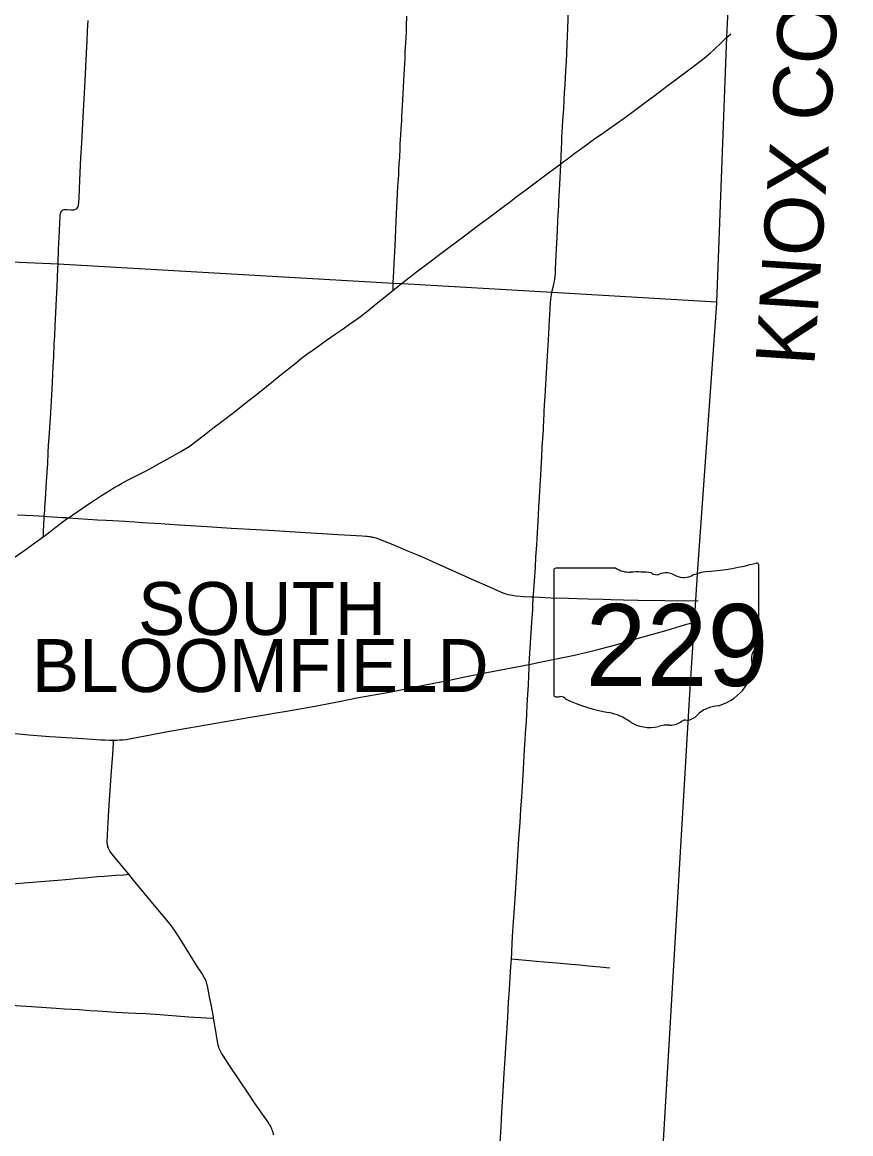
# Model space of a CAD drawing. Extents: x 9078 to 9739, y 4248 to 4966.
# Drawn here: x 9587.6 to 9658, y 4332.5 to 4427 of the extents above; entities that cross this region are included whole.
import ezdxf

# ---------------------------------------------------------------- set-up
doc = ezdxf.new("R2010")
doc.units = 0
for name, color, linetype in [('GM_X_Adjacent_County_Text', 7, 'Continuous'), ('GM_X_County', 7, 'Continuous'), ('GM_X_County_Road', 7, 'Continuous'), ('GM_X_State_Route', 7, 'Continuous'), ('GM_X_State_Shield', 7, 'Continuous'), ('GM_X_Township', 7, 'Continuous'), ('GM_X_Township_Road', 7, 'Continuous'), ('GM_X_Township_Text', 7, 'Continuous')]:
    doc.layers.add(name, color=color, linetype=linetype)

msp = doc.modelspace()

# ---------------------------------------------------------------- linework, layer by layer
at = {"layer": 'GM_X_County'}
msp.add_lwpolyline([(9647.546, 4428.546), (9647.413, 4425.737), (9646.564, 4403.186), (9646.559, 4403.067), (9644.937, 4380.525), (9644.771, 4377.858), (9644.659, 4376.066), (9644.246, 4369.414), (9641.706, 4326.626), (9641.572, 4325.525), (9640.943, 4314.304), (9639.941, 4298.12), (9639.533, 4291.393), (9638.883, 4280.676), (9638.292, 4270.922), (9624.366, 4271.807), (9610.553, 4272.683), (9582.743, 4274.463), (9578.044, 4274.834), (9548.202, 4276.71), (9527.732, 4277.916), (9504.96, 4279.335)], dxfattribs=at)
at = {"layer": 'GM_X_County_Road'}
for points in [[(9633.407, 4416.682), (9633.43, 4417.189), (9633.454, 4417.596), (9633.514, 4418.576), (9633.58, 4419.641), (9633.66, 4420.986), (9633.695, 4421.655), (9633.754, 4422.834), (9633.804, 4423.652), (9633.846, 4424.307), (9633.883, 4425.126), (9633.906, 4425.753), (9633.928, 4426.436), (9633.959, 4427.257), (9633.99, 4427.995), (9634.012, 4428.487), (9634.034, 4428.896), (9634.056, 4429.273), (9634.059, 4429.334)], [(9633.332, 4414.942), (9633.536, 4415.095), (9633.866, 4415.338), (9634.439, 4415.78), (9634.914, 4416.127), (9635.51, 4416.562), (9635.774, 4416.755), (9636.307, 4417.134), (9636.778, 4417.46), (9637.384, 4417.88), (9638.056, 4418.351), (9638.723, 4418.829), (9639.71, 4419.564), (9640.503, 4420.147), (9641.358, 4420.784), (9642.342, 4421.522), (9643.065, 4422.062), (9644.442, 4423.097), (9645.36, 4423.787), (9645.681, 4424.043), (9646.056, 4424.363), (9646.297, 4424.585), (9647, 4425.274), (9647.355, 4425.613), (9647.773, 4425.972)], [(9633.332, 4414.942), (9633.35, 4415.469), (9633.39, 4416.288), (9633.407, 4416.682)], [(9619.77, 4404.734), (9619.905, 4404.843), (9620.42, 4405.25), (9621.07, 4405.749), (9621.723, 4406.246), (9623.033, 4407.232), (9625.267, 4408.902), (9626.118, 4409.544), (9626.578, 4409.887), (9627.17, 4410.327), (9627.631, 4410.666), (9628.089, 4411.012), (9628.937, 4411.658), (9629.525, 4412.105), (9630.248, 4412.644), (9631.501, 4413.571), (9632.288, 4414.162), (9633.332, 4414.942)], [(9633.133, 4410.935), (9633.155, 4411.38), (9633.178, 4411.789), (9633.201, 4412.198), (9633.275, 4413.755), (9633.305, 4414.324), (9633.33, 4414.894), (9633.332, 4414.942)], [(9632.576, 4404.003), (9632.603, 4404.133), (9632.678, 4404.442), (9632.744, 4404.71), (9632.788, 4404.926), (9632.832, 4405.186), (9632.872, 4405.552), (9632.894, 4405.997), (9632.942, 4407.147), (9632.964, 4407.724), (9633.016, 4408.681), (9633.051, 4409.336), (9633.09, 4410.073), (9633.116, 4410.563), (9633.133, 4410.935)], [(9619.091, 4404.19), (9619.77, 4404.734)], [(9591.52, 4384.854), (9591.886, 4385.114), (9592.703, 4385.662), (9593.18, 4385.981), (9593.724, 4386.348), (9594.341, 4386.749), (9594.824, 4387.057), (9595.379, 4387.406), (9595.732, 4387.613), (9596.019, 4387.769), (9596.6, 4388.073), (9596.889, 4388.227), (9597.399, 4388.491), (9598.056, 4388.826), (9598.419, 4389.018), (9599.283, 4389.488), (9599.714, 4389.726), (9600.359, 4390.084), (9601.077, 4390.482), (9601.502, 4390.731), (9601.779, 4390.908), (9601.98, 4391.052), (9602.24, 4391.252), (9603.206, 4392.007), (9603.788, 4392.458), (9604.439, 4392.957), (9605.026, 4393.405), (9605.48, 4393.756), (9605.868, 4394.058), (9606.769, 4394.766), (9607.088, 4395.021), (9607.732, 4395.528), (9608.946, 4396.505), (9609.583, 4397.023), (9610.734, 4397.947), (9611.311, 4398.406), (9611.769, 4398.751), (9612.304, 4399.129), (9612.906, 4399.556), (9613.441, 4399.937), (9614.181, 4400.452), (9614.852, 4400.924), (9615.387, 4401.301), (9615.923, 4401.68), (9616.319, 4401.973), (9616.965, 4402.479), (9617.667, 4403.046), (9618.434, 4403.662), (9619.091, 4404.19)], [(9631.008, 4378.13), (9631.021, 4378.342), (9631.097, 4379.487), (9631.172, 4380.633), (9631.225, 4381.534), (9631.285, 4382.517), (9631.318, 4383.09), (9631.373, 4384.072), (9631.433, 4385.055), (9631.478, 4385.792), (9631.526, 4386.611), (9631.61, 4388.084), (9631.627, 4388.411), (9631.658, 4389.066), (9631.713, 4390.049), (9631.761, 4390.868), (9631.808, 4391.605), (9631.849, 4392.341), (9631.867, 4392.669), (9631.882, 4392.996), (9631.924, 4393.815), (9631.955, 4394.47), (9631.992, 4395.126), (9632.023, 4395.699), (9632.05, 4396.19), (9632.107, 4397.172), (9632.162, 4398.153), (9632.221, 4399.051), (9632.279, 4399.951), (9632.312, 4400.524), (9632.339, 4401.015), (9632.376, 4401.753), (9632.39, 4401.999), (9632.431, 4402.737), (9632.489, 4403.45), (9632.537, 4403.816), (9632.576, 4404.003)], [(9589.383, 4383.25), (9589.456, 4383.303), (9590.046, 4383.745), (9590.629, 4384.197), (9591.419, 4384.782), (9591.52, 4384.854)], [(9591.52, 4384.854), (9592.339, 4384.787), (9593.156, 4384.735), (9593.975, 4384.689), (9594.712, 4384.648), (9596.347, 4384.558), (9597.165, 4384.503), (9597.819, 4384.459), (9598.8, 4384.402), (9599.373, 4384.369), (9600.109, 4384.321), (9600.928, 4384.27), (9603.302, 4384.113), (9605.338, 4383.985), (9607.467, 4383.863), (9609.023, 4383.766), (9611.234, 4383.631), (9614.42, 4383.434), (9616.467, 4383.316), (9616.765, 4383.298), (9616.887, 4383.289), (9617.039, 4383.266), (9617.14, 4383.252), (9617.255, 4383.233), (9617.322, 4383.219), (9617.41, 4383.199), (9617.504, 4383.176), (9617.612, 4383.143), (9617.769, 4383.093), (9618.141, 4382.958), (9619.353, 4382.462), (9620.185, 4382.116), (9620.867, 4381.833), (9621.769, 4381.44), (9622.744, 4381.007), (9626.036, 4379.528), (9627.085, 4379.061), (9628.21, 4378.562), (9628.407, 4378.482), (9628.593, 4378.416), (9628.744, 4378.371), (9628.874, 4378.337), (9629.046, 4378.298), (9629.231, 4378.267), (9629.486, 4378.237), (9629.884, 4378.194), (9630.156, 4378.172), (9630.844, 4378.138), (9631.008, 4378.13)], [(9586.453, 4381.158), (9587.726, 4382.057), (9588.661, 4382.724), (9589.383, 4383.25)], [(9630.656, 4372.402), (9630.657, 4372.449), (9630.712, 4373.35), (9630.906, 4376.379), (9630.946, 4377.034), (9630.968, 4377.443), (9630.999, 4378.015), (9631.008, 4378.13)], [(9631.008, 4378.13), (9632.505, 4378.058), (9633.981, 4378.012), (9634.718, 4377.995), (9635.62, 4377.97), (9636.933, 4377.936), (9637.589, 4377.922), (9638.653, 4377.897), (9639.882, 4377.867), (9642.179, 4377.836), (9644.996, 4377.797)], [(9629.135, 4347.38), (9629.162, 4347.912), (9629.211, 4348.731), (9629.271, 4349.713), (9629.445, 4352.496), (9629.57, 4354.296), (9629.658, 4355.673), (9629.753, 4357.143), (9629.779, 4357.552), (9629.826, 4358.288), (9629.871, 4358.942), (9629.95, 4360.088), (9630.023, 4361.152), (9630.074, 4362.053), (9630.104, 4362.544), (9630.16, 4363.526), (9630.257, 4365.163), (9630.309, 4365.981), (9630.347, 4366.554), (9630.406, 4367.536), (9630.444, 4368.191), (9630.483, 4368.929), (9630.513, 4369.42), (9630.557, 4370.237), (9630.576, 4370.647), (9630.613, 4371.384), (9630.646, 4372.121), (9630.656, 4372.402)], [(9627.886, 4327.412), (9627.948, 4328.25), (9628.066, 4330.13), (9628.174, 4331.764), (9628.257, 4333.072), (9628.3, 4333.807), (9628.359, 4334.788), (9628.435, 4336.096), (9628.529, 4337.649), (9628.58, 4338.466), (9628.636, 4339.365), (9628.716, 4340.673), (9628.826, 4342.389), (9628.901, 4343.697), (9628.965, 4344.76), (9629.066, 4346.312), (9629.135, 4347.38)]]:
    msp.add_lwpolyline(points, dxfattribs=at)
at = {"layer": 'GM_X_State_Route'}
msp.add_lwpolyline([(9586.691, 4366.542), (9588.159, 4366.411), (9589.952, 4366.276), (9592.324, 4366.122), (9593.552, 4366.042), (9594.26, 4365.996), (9594.612, 4365.976), (9595.005, 4365.961), (9595.351, 4365.956), (9595.606, 4365.963), (9595.86, 4365.972), (9596.128, 4365.994), (9596.412, 4366.023), (9597.138, 4366.143), (9598.49, 4366.42), (9599.779, 4366.671), (9600.91, 4366.868), (9605.519, 4367.663), (9606.812, 4367.886), (9608.025, 4368.086), (9608.995, 4368.251), (9610.046, 4368.433), (9611.825, 4368.735), (9613.357, 4369.016), (9614.642, 4369.281), (9616.01, 4369.555), (9618.916, 4370.079), (9621.007, 4370.49), (9621.967, 4370.681), (9623.752, 4371.036), (9625.19, 4371.326), (9627.04, 4371.694), (9630.656, 4372.402), (9631.555, 4372.578), (9634.36, 4373.152), (9635.56, 4373.426), (9636.595, 4373.681), (9638.019, 4374.069), (9640.226, 4374.702), (9642.355, 4375.312), (9643.843, 4375.75), (9644.887, 4376.05)], dxfattribs=at)
at = {"layer": 'GM_X_State_Shield'}
for p, q in [((9632.735, 4380.386), (9632.735, 4369.82)), ((9638.003, 4380.568), (9632.906, 4380.568)), ((9650.137, 4375.303), (9650.137, 4380.83)), ((9650.135, 4375.304), (9650.137, 4375.303))]:
    msp.add_line(p, q, dxfattribs=at)
for centre, major_axis, start_param, end_param in [((9643.938, 4394.974), (18.455, 0), 4.814394, 5.042369), ((9649.944, 4380.853), (0.194, 0), 6.141152, 7.989035), ((9632.935, 4380.409), (0.202, 0), 1.712693, 3.28349), ((9639.216, 4381.795), (1.955, 0), 4.042523, 4.731795), ((9639.865, 4374.636), (7.02, 0), 1.404758, 1.657858), ((9641.458, 4380.464), (0.564, 0), 3.836095, 5.185415), ((9642.287, 4379.242), (1.173, 0), 0.950623, 2.079405), ((9646.292, 4377.341), (3.713, 0), 1.699011, 2.107814), ((9643.8, 4380.917), (1.411, 0), 4.081561, 5.145723), ((9650.092, 4374.897), (0.3, 0), 1.883978, 3.671073), ((9648.185, 4374.198), (1.8, 0), 5.934695, 6.695948), ((9649.93, 4375.281), (0.207, 0), 5.05454, 6.418171), ((9650.831, 4372.99), (1.309, 0), 2.387724, 3.262537), ((9644.972, 4372.286), (4.616, 0), 5.101752, 6.440018), ((9632.936, 4369.797), (0.203, 0), 3.00124, 4.508301), ((9633.285, 4369.21), (0.56, 0), 0.519207, 1.627899), ((9632.967, 4370.878), (1.552, 0), 4.665946, 4.897461), ((9640.351, 4378.704), (13.327, 0), 4.195997, 4.488961), ((9646.918, 4366.854), (2.528, 0), 1.647645, 2.488434), ((9636.378, 4365.073), (4.17, 0), 0.823519, 1.323587), ((9643.715, 4368.796), (1.491, 0), 4.937069, 5.64225), ((9640.887, 4369.158), (2.646, 0), 4.026481, 4.996735), ((9642.416, 4365.505), (2.174, 0), 1.495662, 1.94098), ((9642.609, 4368.367), (1.41, 0), 4.691044, 5.507374), ((9643.885, 4367.343), (0.397, 0), 1.147584, 2.315152)]:
    msp.add_ellipse(centre, major_axis=major_axis, ratio=0.8, start_param=start_param, end_param=end_param, dxfattribs=at)
at = {"layer": 'GM_X_Township'}
msp.add_lwpolyline([(9646.564, 4403.186), (9632.593, 4403.992), (9619.889, 4404.725), (9619.129, 4404.769), (9590.635, 4406.413), (9575.396, 4407.069), (9562.089, 4407.805), (9537.409, 4409.337), (9510.323, 4411.058), (9511.38, 4427.966), (9511.83, 4435.772), (9511.888, 4436.239), (9513.121, 4453.992), (9514.674, 4478.861), (9516.207, 4506.231), (9517.263, 4528.671), (9517.499, 4532.736), (9518.307, 4546.633)], dxfattribs=at)
at = {"layer": 'GM_X_Township_Road'}
for points in [[(9619.098, 4404.781), (9619.119, 4405.348), (9619.145, 4405.758), (9619.193, 4406.489), (9619.263, 4407.957), (9619.329, 4409.349), (9619.392, 4410.742), (9619.438, 4411.725), (9619.501, 4413.036), (9619.542, 4413.608), (9619.564, 4414.067), (9619.589, 4414.426), (9619.618, 4414.917), (9619.653, 4415.488), (9619.685, 4416.223), (9619.705, 4416.632), (9619.747, 4417.368), (9619.781, 4417.941), (9619.82, 4418.595), (9619.844, 4418.921), (9619.896, 4419.902), (9619.946, 4420.884), (9620.014, 4422.03), (9620.032, 4422.513), (9620.055, 4423.01), (9620.105, 4423.909), (9620.129, 4424.481), (9620.165, 4425.218), (9620.216, 4426.117), (9620.239, 4426.675), (9620.251, 4427.472)], [(9590.644, 4406.422), (9590.691, 4407.688), (9590.752, 4409.223), (9590.783, 4409.949), (9590.816, 4410.413), (9590.831, 4410.579), (9590.852, 4410.705), (9590.873, 4410.784), (9590.903, 4410.861), (9590.945, 4410.931), (9591.004, 4410.988), (9591.076, 4411.025), (9591.156, 4411.046), (9591.237, 4411.057), (9591.319, 4411.059), (9591.401, 4411.057), (9591.729, 4411.028), (9591.893, 4411.022), (9591.975, 4411.027), (9592.055, 4411.044), (9592.13, 4411.074), (9592.2, 4411.117), (9592.26, 4411.173), (9592.309, 4411.239), (9592.346, 4411.311), (9592.372, 4411.389), (9592.389, 4411.469), (9592.406, 4411.633), (9592.42, 4412.043), (9592.475, 4413.519), (9592.54, 4414.83), (9592.58, 4415.486), (9592.657, 4416.714), (9592.783, 4418.926), (9592.83, 4419.91), (9592.963, 4422.532), (9592.993, 4423.188), (9593.054, 4424.335), (9593.109, 4425.4), (9593.152, 4426.237), (9593.192, 4427.121)], [(9589.471, 4384.985), (9589.503, 4385.463), (9589.527, 4385.79), (9589.57, 4386.403), (9589.608, 4386.961), (9589.666, 4387.919), (9589.716, 4388.738), (9589.761, 4389.476), (9589.806, 4390.377), (9589.839, 4391.033), (9589.881, 4391.688), (9589.94, 4392.507), (9590.012, 4393.768), (9590.076, 4394.802), (9590.138, 4395.785), (9590.202, 4397.015), (9590.235, 4397.753), (9590.273, 4398.491), (9590.322, 4399.64), (9590.352, 4400.296), (9590.393, 4401.198), (9590.447, 4402.264), (9590.505, 4403.495), (9590.552, 4404.479), (9590.629, 4406.037), (9590.644, 4406.422)], [(9619.091, 4404.19), (9619.094, 4404.418), (9619.097, 4404.703), (9619.098, 4404.781)], [(9587.183, 4385.11), (9588.494, 4385.045), (9589.471, 4384.985)], [(9589.383, 4383.25), (9589.391, 4383.43), (9589.398, 4383.595), (9589.442, 4384.335), (9589.463, 4384.777), (9589.471, 4384.972), (9589.471, 4384.985)], [(9589.471, 4384.985), (9589.722, 4384.969), (9590.623, 4384.912), (9591.008, 4384.888), (9591.319, 4384.869), (9591.52, 4384.854)], [(9596.637, 4354.566), (9595.737, 4355.642), (9595.229, 4356.284), (9595.131, 4356.423), (9595.074, 4356.501), (9595.012, 4356.599), (9594.985, 4356.646), (9594.962, 4356.694), (9594.932, 4356.757), (9594.909, 4356.813), (9594.878, 4356.898), (9594.857, 4356.976), (9594.841, 4357.05), (9594.832, 4357.095), (9594.825, 4357.142), (9594.821, 4357.182), (9594.817, 4357.232), (9594.816, 4357.295), (9594.818, 4357.393), (9594.819, 4357.494), (9594.826, 4357.671), (9594.839, 4357.936), (9594.866, 4358.467), (9594.893, 4358.929), (9594.959, 4360.004), (9595.135, 4362.539), (9595.212, 4363.682), (9595.284, 4364.745), (9595.345, 4365.727), (9595.351, 4365.956)], [(9586.783, 4353.749), (9588.094, 4353.849), (9588.503, 4353.882), (9589.156, 4353.94), (9589.892, 4354.011), (9590.628, 4354.074), (9591.284, 4354.125), (9591.903, 4354.176), (9592.347, 4354.217), (9592.92, 4354.264), (9593.984, 4354.358), (9594.557, 4354.402), (9595.539, 4354.475), (9596.195, 4354.521), (9596.44, 4354.546), (9596.637, 4354.566)], [(9603.848, 4342.328), (9603.828, 4342.444), (9603.633, 4343.49), (9603.508, 4344.133), (9603.418, 4344.621), (9603.362, 4344.902), (9603.316, 4345.11), (9603.287, 4345.229), (9603.25, 4345.365), (9603.208, 4345.487), (9603.152, 4345.613), (9603.058, 4345.794), (9602.853, 4346.15), (9602.49, 4346.697), (9602.049, 4347.386), (9601.15, 4348.854), (9600.526, 4349.818), (9600.239, 4350.219), (9599.874, 4350.663), (9598.82, 4351.917), (9597.051, 4354.07), (9596.637, 4354.566)], [(9629.135, 4347.38), (9631.263, 4347.188), (9631.918, 4347.13), (9632.984, 4347.039), (9634.212, 4346.926), (9634.948, 4346.852), (9635.685, 4346.782), (9636.667, 4346.689), (9637.486, 4346.614)], [(9583.592, 4343.628), (9589.238, 4343.271), (9590.465, 4343.197), (9591.2, 4343.139), (9592.427, 4343.061), (9593.326, 4342.996), (9593.981, 4342.955), (9594.799, 4342.905), (9595.535, 4342.853), (9596.599, 4342.797), (9597.253, 4342.763), (9598.072, 4342.717), (9599.273, 4342.632), (9600.688, 4342.53), (9601.751, 4342.454), (9603.223, 4342.359), (9603.737, 4342.334), (9603.848, 4342.328)], [(9608.958, 4332.388), (9608.872, 4332.69), (9608.825, 4332.826), (9608.786, 4332.934), (9608.743, 4333.041), (9608.671, 4333.185), (9608.598, 4333.306), (9608.528, 4333.414), (9608.281, 4333.787), (9607.389, 4335.063), (9606.834, 4335.875), (9605.196, 4338.312), (9604.737, 4339.014), (9604.524, 4339.357), (9604.428, 4339.531), (9604.372, 4339.644), (9604.324, 4339.76), (9604.288, 4339.86), (9604.241, 4340.025), (9604.209, 4340.187), (9604.035, 4341.237), (9603.848, 4342.328)]]:
    msp.add_lwpolyline(points, dxfattribs=at)

# ---------------------------------------------------------------- texts
at = {"layer": 'GM_X_Adjacent_County_Text'}
msp.add_text('KNOX COUNTY', height=5, rotation=86.22308, dxfattribs=at).set_placement((9654.852, 4397.684))
at = {"layer": 'GM_X_State_Shield'}
msp.add_text('229', height=6.961, dxfattribs=at).set_placement((9635.434, 4370.565))
at = {"layer": 'GM_X_Township_Text'}
for s, p in [('SOUTH', (9597.434, 4374.896)), ('BLOOMFIELD', (9588.414, 4370.05))]:
    msp.add_text(s, height=4.5, rotation=0.00001, dxfattribs=at).set_placement(p)

doc.saveas('drawing.dxf')
